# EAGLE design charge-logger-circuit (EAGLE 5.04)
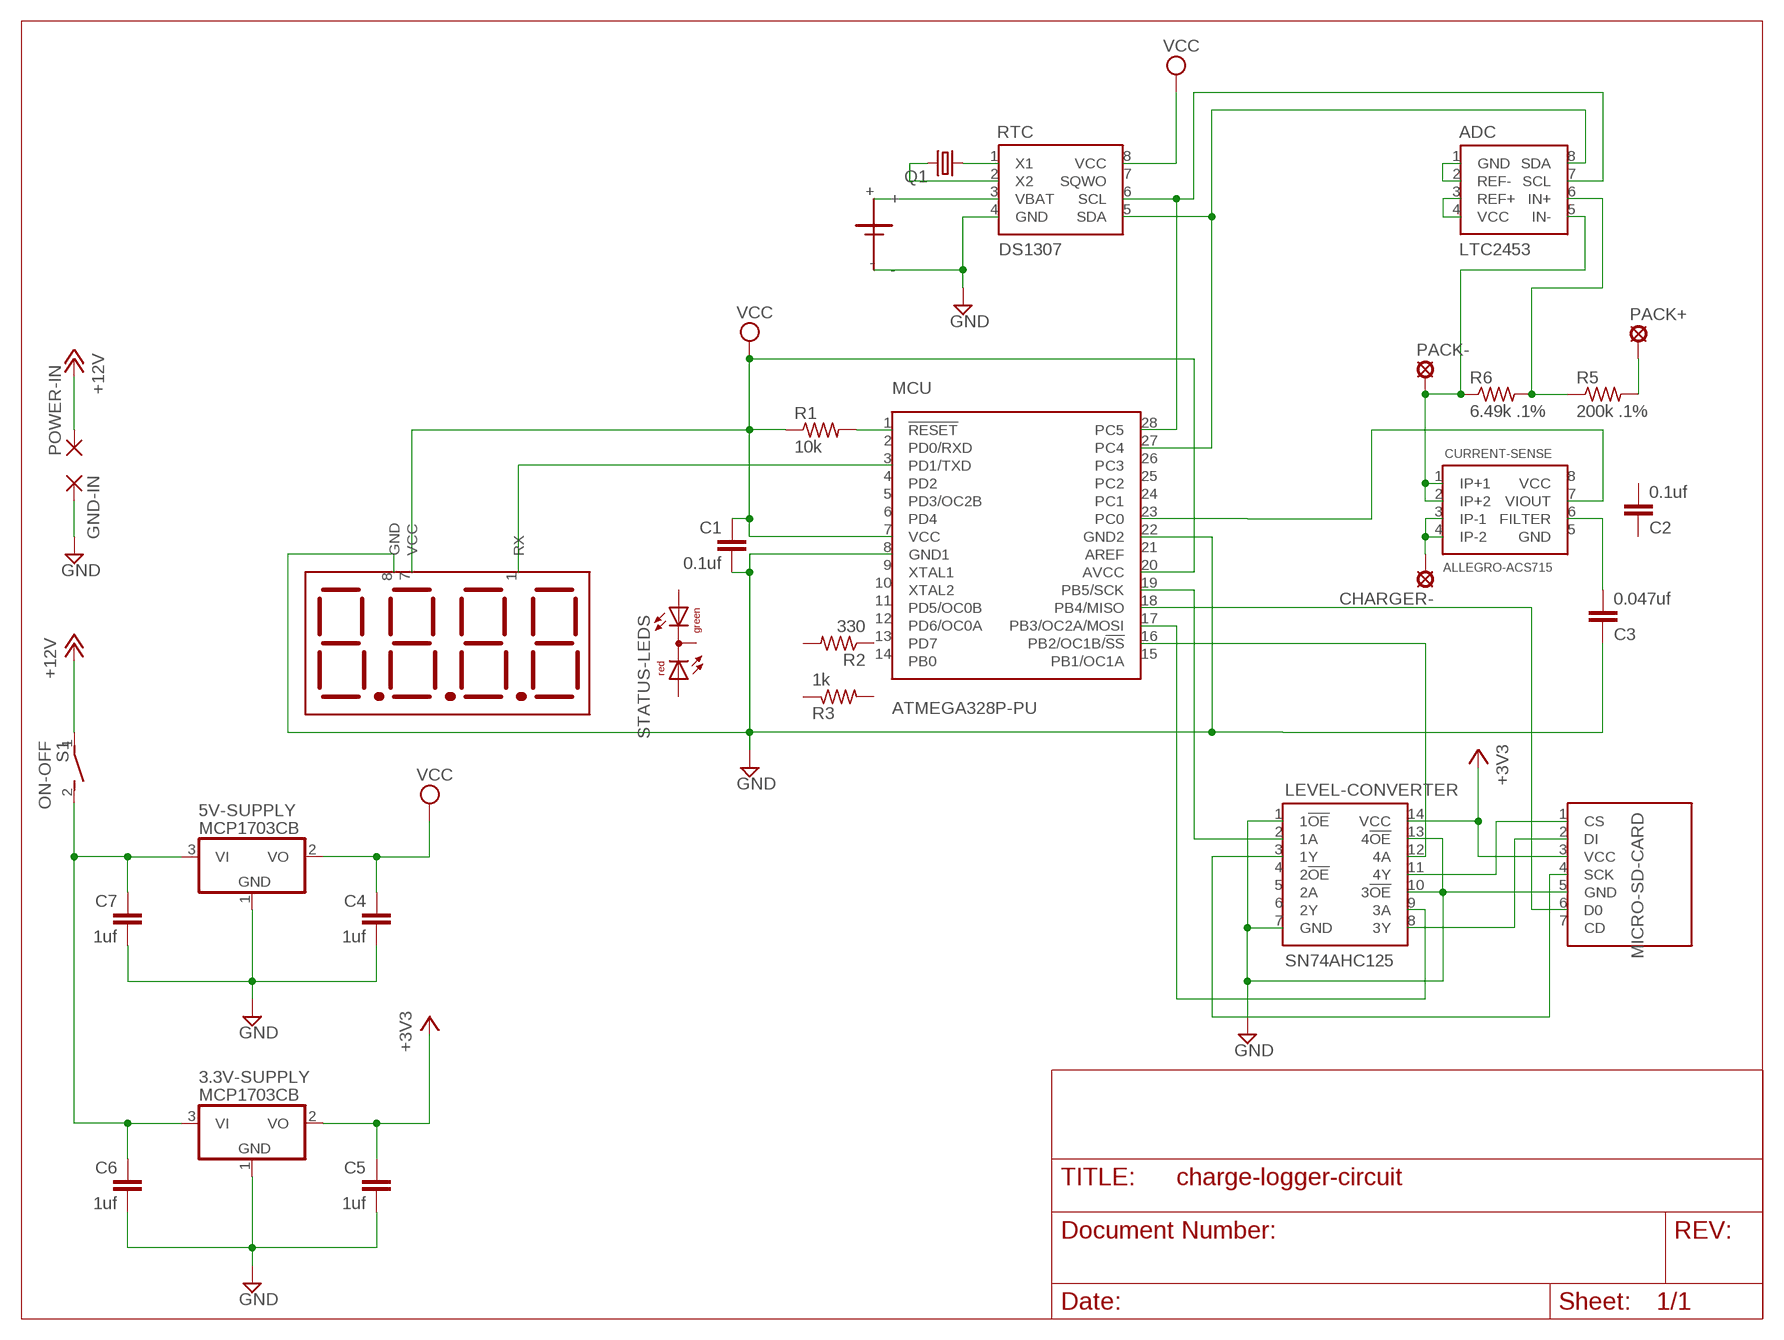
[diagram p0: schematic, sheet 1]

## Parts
3.3V-SUPPLY  MCP1703CB  [SOT23]
5V-SUPPLY  MCP1703CB  [SOT23]
ADC  LTC2453  [8TSOT23]
C1  0.1uf  C2.5/2  [C2.5-2]
C2  0.1uf  C2.5/2  [C2.5-2]
C3  0.047uf  C2.5/2  [C2.5-2]
C4  1uf  C2.5/2  [C2.5-2]
C5  1uf  C2.5/2  [C2.5-2]
C6  1uf  C2.5/2  [C2.5-2]
C7  1uf  C2.5/2  [C2.5-2]
CHARGER-  SE14  [SE14]
CURRENT-SENSE  ALLEGRO-ACS715  [8SOIC]
GND-IN  1,6/0,8  [1,6/0,8]
LEVEL-CONVERTER  SN74AHC125  [DIP14]
MCU  ATMEGA328P-PU  [DIL28-3]
MICRO-SD-CARD  SFE-MICRO-SD-CARD-BREAKOUT  [SFE-MICRO-SD-CARD-BREAKOUT]
PACK+  SE14  [SE14]
PACK-  SE14  [SE14]
POWER-IN  1,6/0,8  [1,6/0,8]
Q1  CRYSTALTC26V  [TC26V]
R1  10k  R-US_0204/5  [0204/5]
R2  330  R-US_0204/5  [0204/5]
R3  1k  R-US_0204/5  [0204/5]
R5  200k .1%  R-US_M1206  [M1206]
R6  6.49k .1%  R-US_M1206  [M1206]
RTC  DS1307  [DIL8-3]
S1  ON-OFF  DS01E  [DS-01]
STATUS-LEDS  DUOLED2X5  [DUOLED2X5]
U$1  4-DIGIT-DISPLAY  [3SIL-OF-8]
U$3  BATTERY-COIN-16MM  [BATTERY-COIN-16MM]

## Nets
+3V3: 3.3V-SUPPLY.2(VO) C5.1 LEVEL-CONVERTER.14(VCC) MICRO-SD-CARD.3(VCC)
+12V: POWER-IN.1(P) S1.1
GND: 3.3V-SUPPLY.1(GND) 5V-SUPPLY.1(GND) C1.2 C3.1 C4.2 C5.2 C6.2 C7.2 GND-IN.1(P) LEVEL-CONVERTER.1(1!OE) LEVEL-CONVERTER.7(GND) LEVEL-CONVERTER.10(3!OE) LEVEL-CONVERTER.13(4!OE) MCU.8(GND1) MCU.22(GND2) MICRO-SD-CARD.5(GND) RTC.4(GND) U$1.8(GND) U$3.-
N$1: MCU.1(!RESET) R1.2
N$2: Q1.1 RTC.1(X1)
N$3: Q1.2 RTC.2(X2)
N$4: ADC.3(REF+) ADC.4(VCC)
N$5: ADC.1(GND) ADC.2(REF-)
N$8: RTC.3(VBAT) U$3.+
N$9: MCU.3(PD1/TXD) U$1.1(RX)
N$10: CURRENT-SENSE.7(VIOUT) MCU.23(PC0)
N$11: PACK+.MP R5.2
N$12: CHARGER-.MP CURRENT-SENSE.3(IP-1) CURRENT-SENSE.4(IP-2)
N$14: 3.3V-SUPPLY.3(VI) 5V-SUPPLY.3(VI) C6.1 C7.1 S1.2
N$15: ADC.7(SCL) MCU.28(PC5) RTC.6(SCL)
N$16: ADC.8(SDA) MCU.27(PC4) RTC.5(SDA)
N$18: C3.2 CURRENT-SENSE.6(FILTER)
N$19: ADC.6(IN+) R5.1 R6.2
N$20: ADC.5(IN-) CURRENT-SENSE.1(IP+1) CURRENT-SENSE.2(IP+2) PACK-.MP R6.1
N$21: MCU.18(PB4/MISO) MICRO-SD-CARD.6(D0)
N$22: LEVEL-CONVERTER.2(1A) MCU.19(PB5/SCK)
N$23: LEVEL-CONVERTER.9(3A) MCU.17(PB3/OC2A/MOSI)
N$24: LEVEL-CONVERTER.12(4A) MCU.16(PB2/OC1B/!SS)
N$25: LEVEL-CONVERTER.11(4Y) MICRO-SD-CARD.1(CS)
N$26: LEVEL-CONVERTER.8(3Y) MICRO-SD-CARD.2(DI)
N$27: LEVEL-CONVERTER.3(1Y) MICRO-SD-CARD.4(SCK)
VCC: 5V-SUPPLY.2(VO) C1.1 C4.1 MCU.7(VCC) MCU.20(AVCC) R1.1 RTC.8(VCC) U$1.7(VCC)
Unconnected: C2.1 C2.2 CURRENT-SENSE.5(GND) CURRENT-SENSE.8(VCC) LEVEL-CONVERTER.4(2!OE) LEVEL-CONVERTER.5(2A) LEVEL-CONVERTER.6(2Y) MCU.2(PD0/RXD) MCU.4(PD2) MCU.5(PD3/OC2B) MCU.6(PD4) MCU.9(XTAL1) MCU.10(XTAL2) MCU.11(PD5/OC0B) MCU.12(PD6/OC0A) MCU.13(PD7) MCU.14(PB0) MCU.15(PB1/OC1A) MCU.21(AREF) MCU.24(PC1) MCU.25(PC2) MCU.26(PC3) MICRO-SD-CARD.7(CD) R2.1 R2.2 R3.1 R3.2 RTC.7(SQWO) STATUS-LEDS.AG STATUS-LEDS.AR STATUS-LEDS.K(C)

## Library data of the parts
3.3V-SUPPLY 5V-SUPPLY = linear:MCP1703: 250 mA, 16V, Low Quiescent Current LDO Regulator Source: http://ww1.microchip.com/downloads/en/DeviceDoc/22049b.pdf
ADC = trl:LTC2453
C1-C7 = capacitor-wima:C: CAPACITOR
CHARGER- PACK+ PACK- = solpad:SE14: SOLDER PAD
CURRENT-SENSE = trl:ALLEGRO-ACS715
GND-IN POWER-IN = wirepad:1,6/0,8: THROUGH-HOLE PAD
LEVEL-CONVERTER = trl:SN74AHC125
MCU = trl:ATMEGA328P-PU
MICRO-SD-CARD = trl:SFE-MICRO-SD-CARD-BREAKOUT
Q1 = crystal:CRYSTAL: CRYSTAL
R1-R3 R5 R6 = resistor:R-US_: RESISTOR, American symbol
RTC = trl:DS1307
S1 = switch-dil:DS01E: DIL/CODE SWITCH
STATUS-LEDS = led:DUOLED2X5: DUO LED 2 colors, 2.5 x 5 mm, recangle
U$1 = trl:4-DIGIT-DISPLAY
U$3 = trl:BATTERY-COIN-16MM

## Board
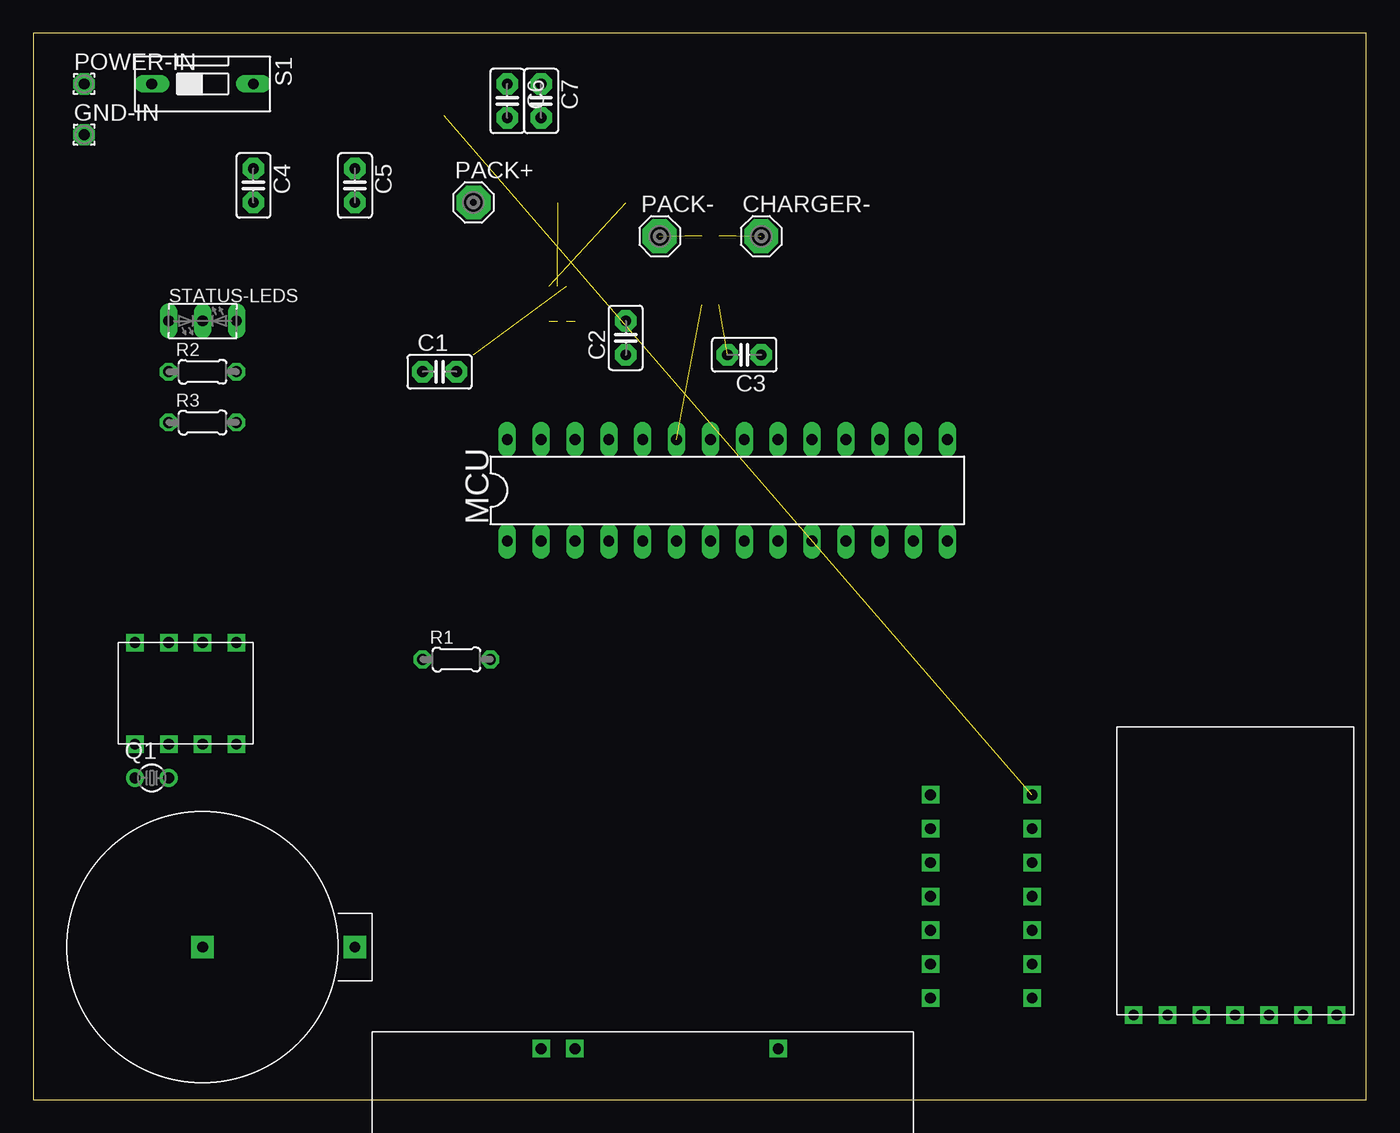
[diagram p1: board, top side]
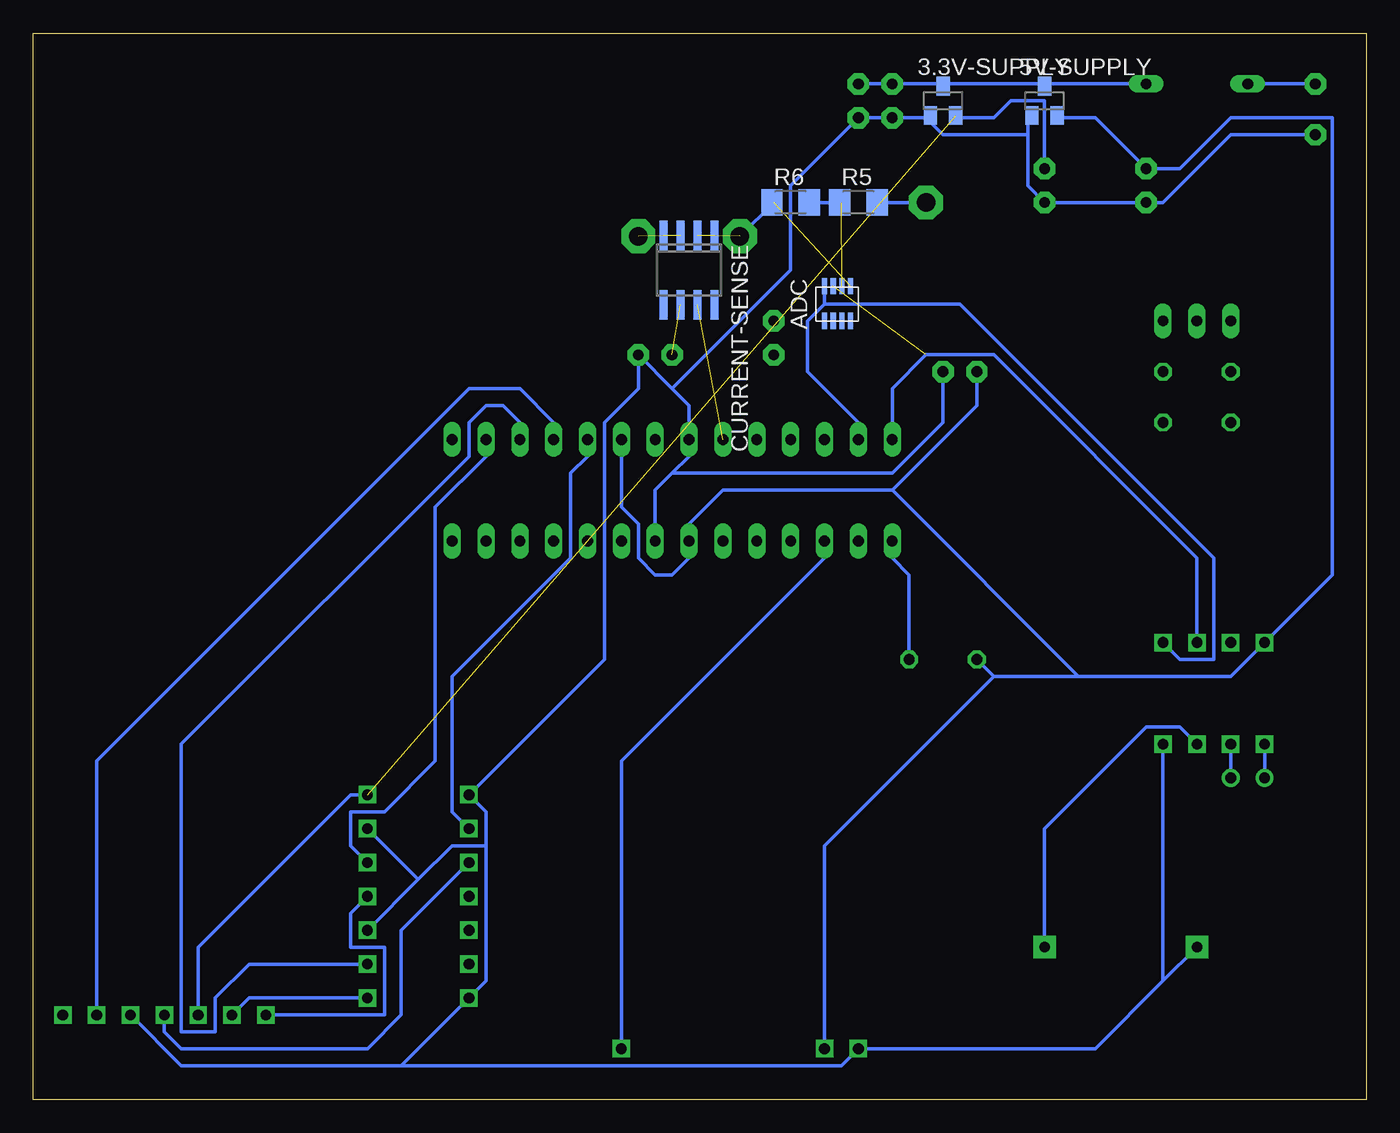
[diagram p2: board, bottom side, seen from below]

Size 100 x 80 mm. Coordinates in mm from the lower left corner, seen from the top.
Outline: 0,0 100,0 100,80 0,80 0,0
Copper layers (1*16): Top 0.035mm / dielectric 1.5mm / Bottom 0.035mm
Design rules "default": minimum track width 10mil, minimum drill 24mil, track to track 8mil, track to pad 8mil, pad to pad 8mil, via to via 8mil, smd to smd 8mil, copper to edge 40mil, drill to drill 8mil, minimum pad ring 10mil, minimum via ring 8mil, stop-mask expansion 4mil, vias tented up to drill 0mil, thermal gap 10mil

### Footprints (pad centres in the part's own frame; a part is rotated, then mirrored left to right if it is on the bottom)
SOT23 = smd 1 x 1.4: 1 -0.95,-1.1; 2 0.95,-1.1; 3 0,1.1
8TSOT23 = smd 0.381 x 1.22: 1 -1.27,-1.27; 2 -0.62,-1.27; 3 0.03,-1.27; 4 0.68,-1.27; 5 0.68,1.35; 6 0.03,1.35; 7 -0.62,1.35; 8 -1.27,1.35
C2.5-2 = drill 0.813 pad 1.6 octagon: 1 -1.27,0; 2 1.27,0
SE14 = drill 1.397 pad 2.54 octagon: MP 0,0
8SOIC = smd 0.6 x 2.2: 1 -1.905,-2.6; 2 -0.635,-2.6; 3 0.635,-2.6; 4 1.905,-2.6; 5 1.905,2.6; 6 0.635,2.6; 7 -0.635,2.6; 8 -1.905,2.6
1,6/0,8 = drill 0.813 pad 1.6 octagon: 1 0,0
DIP14 = drill 0.8 square: 1 -3.81,6.35; 2 -3.81,3.81; 3 -3.81,1.27; 4 -3.81,-1.27; 5 -3.81,-3.81; 6 -3.81,-6.35; 7 -3.81,-8.89; 8 3.81,-8.89; 9 3.81,-6.35; 10 3.81,-3.81; 11 3.81,-1.27; 12 3.81,1.27; 13 3.81,3.81; 14 3.81,6.35
DIL28-3 = drill 0.813 long: 1 -16.51,-3.81; 2 -13.97,-3.81; 3 -11.43,-3.81; 4 -8.89,-3.81; 5 -6.35,-3.81; 6 -3.81,-3.81; 7 -1.27,-3.81; 8 1.27,-3.81; 9 3.81,-3.81; 10 6.35,-3.81; 11 8.89,-3.81; 12 11.43,-3.81; 13 13.97,-3.81; 14 16.51,-3.81; 15 16.51,3.81; 16 13.97,3.81; 17 11.43,3.81; 18 8.89,3.81; 19 6.35,3.81; 20 3.81,3.81; 21 1.27,3.81; 22 -1.27,3.81; 23 -3.81,3.81; 24 -6.35,3.81; 25 -8.89,3.81; 26 -11.43,3.81; 27 -13.97,3.81; 28 -16.51,3.81
SFE-MICRO-SD-CARD-BREAKOUT = drill 0.8 square: 1 -7.62,-10.16; 2 -5.08,-10.16; 3 -2.54,-10.16; 4 0,-10.16; 5 2.54,-10.16; 6 5.08,-10.16; 7 7.62,-10.16
TC26V = drill 0.813 round: 1 -1.27,0; 2 1.27,0
0204/5 = drill 0.813 octagon: 1 -2.54,0; 2 2.54,0
M1206 = smd 1.6 x 2: 1 -1.4,0; 2 1.4,0
DIL8-3 = drill 0.8 square: 1 -3.81,3.81; 2 -3.81,1.27; 3 -3.81,-1.27; 4 -3.81,-3.81; 5 3.81,-3.81; 6 3.81,-1.27; 7 3.81,1.27; 8 3.81,3.81
DS-01 = drill 0.813 long: 1 0,-3.81; 2 0,3.81
DUOLED2X5 = drill 0.813 long: AG -2.54,0; AR 2.54,0; K 0,0
3SIL-OF-8 = drill 0.8 square: 1 30.48,-1.27; 7 15.24,-1.27; 8 12.7,-1.27
BATTERY-COIN-16MM = drill 0.8 pad 1.676 square: + 11.43,0; - 0,0

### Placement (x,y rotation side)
3.3V-SUPPLY  31.75,74.93 0 bottom
5V-SUPPLY  24.13,74.93 0 bottom
ADC  39.37,59.69 0 bottom
C1  30.48,54.61 0 top
C2  44.45,57.15 90 top
C3  53.34,55.88 180 top
C4  16.51,68.58 270 top
C5  24.13,68.58 270 top
C6  35.56,74.93 270 top
C7  38.1,74.93 270 top
CHARGER-  54.61,64.77 0 top
CURRENT-SENSE  50.8,62.23 180 bottom
GND-IN  3.81,72.39 0 top
LEVEL-CONVERTER  71.12,16.51 0 top
MCU  52.07,45.72 0 top
MICRO-SD-CARD  90.17,16.51 0 top
PACK+  33.02,67.31 0 top
PACK-  46.99,64.77 0 top
POWER-IN  3.81,76.2 0 top
Q1  8.89,24.13 0 top
R1  31.75,33.02 0 top
R2  12.7,54.61 0 top
R3  12.7,50.8 0 top
R5  38.1,67.31 0 bottom
R6  43.18,67.31 0 bottom
RTC  11.43,30.48 90 top
S1  12.7,76.2 270 top
STATUS-LEDS  12.7,58.42 0 top
U$1  25.4,5.08 0 top
U$3  12.7,11.43 0 top

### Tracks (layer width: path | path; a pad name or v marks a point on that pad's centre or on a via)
+3V3  (1 unrouted)
  Bottom 0.254: LEVEL-CONVERTER.14 76.2,22.86 87.63,11.43 MICRO-SD-CARD.3 | C5.1 24.13,74.93 26.67,74.93 27.94,73.66 30.48,73.66 3.3V-SUPPLY.2
+12V
  Bottom 0.254: POWER-IN.1 7.62,76.2 S1.1
GND
  Bottom 0.254: U$3.- 15.24,8.89 | 15.24,8.89 20.32,3.81 U$1.8 39.37,2.54 72.39,2.54 | 15.24,8.89 RTC.4 | 33.02,73.66 C6.2 C7.2 43.18,68.58 43.18,62.23 52.07,53.34 | 33.02,73.66 3.3V-SUPPLY.1 33.02,73.66 | 25.4,72.39 25.4,68.58 C5.2 C4.2 15.24,67.31 10.16,72.39 GND-IN.1 | 25.4,72.39 25.4,73.66 5V-SUPPLY.1 | 33.02,73.66 31.75,72.39 25.4,72.39 | 52.07,46.99 50.8,48.26 MCU.22 50.8,50.8 50.8,52.07 52.07,53.34 | 52.07,46.99 53.34,45.72 53.34,43.18 MCU.8 | C1.2 31.75,50.8 35.56,46.99 52.07,46.99 | 52.07,53.34 C3.1 54.61,53.34 57.15,50.8 57.15,33.02 LEVEL-CONVERTER.1 66.04,21.59 66.04,19.05 | 66.04,19.05 66.04,8.89 LEVEL-CONVERTER.7 72.39,2.54 | MICRO-SD-CARD.5 88.9,2.54 72.39,2.54 | 71.12,16.51 68.58,19.05 66.04,19.05 | 71.12,16.51 LEVEL-CONVERTER.10 | 71.12,16.51 LEVEL-CONVERTER.13
N$1
  Bottom 0.254: R1.2 34.29,39.37 35.56,40.64 MCU.1
N$2
  Bottom 0.254: Q1.1 RTC.1
N$3
  Bottom 0.254: Q1.2 RTC.2
N$4  (1 unrouted)
N$5  (1 unrouted)
N$8
  Bottom 0.254: RTC.3 13.97,27.94 16.51,27.94 24.13,20.32 U$3.+
N$9
  Bottom 0.254: U$1.1 55.88,25.4 40.64,40.64 MCU.3
N$10  (1 unrouted)
N$11
  Bottom 0.254: PACK+.MP R5.2 | R5.2 36.83,67.31 R5.2
N$12  (2 unrouted)
N$14
  Bottom 0.254: 31.75,76.2 C6.1 C7.1 | 31.75,76.2 3.3V-SUPPLY.3 31.75,76.2 | 24.13,76.2 17.78,76.2 S1.2 | 24.13,76.2 5V-SUPPLY.3 24.13,76.2 | 24.13,76.2 31.75,76.2
N$15  (1 unrouted)
  Bottom 0.254: RTC.6 12.7,40.64 27.94,55.88 33.02,55.88 35.56,53.34 35.56,50.8 MCU.28
N$16
  Bottom 0.254: 40.64,59.69 40.64,60.96 ADC.8 | 40.64,59.69 41.91,58.42 41.91,54.61 38.1,50.8 MCU.27 | RTC.5 13.97,33.02 11.43,33.02 11.43,40.64 30.48,59.69 40.64,59.69
N$18  (1 unrouted)
N$19  (1 unrouted)
  Bottom 0.254: R6.2 41.91,67.31 R6.2 | R5.1 R6.2 | R5.1 39.37,67.31 R5.1
N$20  (3 unrouted)
  Bottom 0.254: PACK-.MP 44.45,67.31 R6.1
N$21
  Bottom 0.254: MICRO-SD-CARD.6 95.25,25.4 67.31,53.34 63.5,53.34 60.96,50.8 MCU.18
N$22
  Bottom 0.254: LEVEL-CONVERTER.2 68.58,21.59 68.58,31.75 59.69,40.64 59.69,46.99 58.42,48.26 MCU.19
N$23
  Bottom 0.254: LEVEL-CONVERTER.9 83.82,10.16 86.36,7.62 86.36,5.08 88.9,5.08 88.9,26.67 67.31,48.26 67.31,50.8 66.04,52.07 64.77,52.07 63.5,50.8 MCU.17
N$24
  Bottom 0.254: LEVEL-CONVERTER.12 76.2,19.05 76.2,21.59 73.66,21.59 69.85,25.4 69.85,44.45 66.04,48.26 MCU.16
N$25
  Bottom 0.254: MICRO-SD-CARD.1 73.66,6.35 73.66,11.43 76.2,11.43 76.2,13.97 LEVEL-CONVERTER.11
N$26
  Bottom 0.254: LEVEL-CONVERTER.8 83.82,7.62 MICRO-SD-CARD.2
N$27
  Bottom 0.254: LEVEL-CONVERTER.3 72.39,12.7 72.39,6.35 74.93,3.81 88.9,3.81 90.17,5.08 MICRO-SD-CARD.4
VCC
  Bottom 0.254: 35.56,45.72 48.26,45.72 50.8,43.18 MCU.7 50.8,40.64 52.07,39.37 53.34,39.37 54.61,40.64 54.61,43.18 55.88,44.45 55.88,48.26 MCU.20 | 35.56,45.72 29.21,52.07 C1.1 | 5V-SUPPLY.2 22.86,73.66 20.32,73.66 C4.1 13.97,69.85 10.16,73.66 2.54,73.66 2.54,39.37 RTC.8 10.16,31.75 21.59,31.75 | 21.59,31.75 27.94,31.75 | 27.94,31.75 R1.1 | U$1.7 40.64,19.05 27.94,31.75 | 21.59,31.75 35.56,45.72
